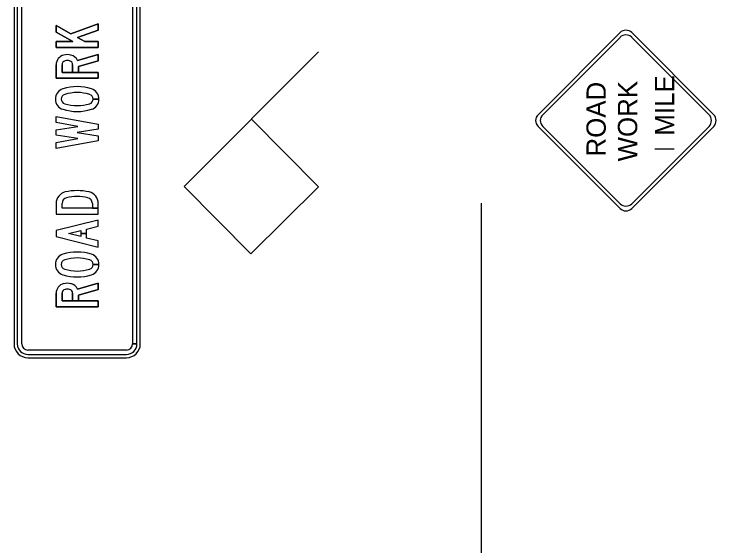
# Model space of a CAD drawing. Extents: x 2155255 to 2162649, y 140388 to 141878.
# Drawn here: x 2156921.6 to 2157021.8, y 141260.5 to 141336.3 of the extents above; entities that cross this region are included whole.
import ezdxf

# ---------------------------------------------------------------- set-up
doc = ezdxf.new("R2010")
doc.units = 0
for name, color, linetype in [('5', 7, 'Continuous'), ('Default', 7, 'Continuous'), ('GSBWFILL', 7, 'Continuous'), ('PR_Dimensions1', 7, 'Continuous'), ('PR_Traffic_Control_Devices_Temp', 7, 'Continuous')]:
    doc.layers.add(name, color=color, linetype=linetype)

# ---------------------------------------------------------------- blocks, each defined once
blk = doc.blocks.new('Cw20-1')
at = {"layer": '5'}
for p, q in [((0.318, 3.005), (2.651, 5.339)), ((5.338, 3.005), (3.005, 5.339)), ((2.651, 0.318), (0.318, 2.652)), ((3.005, 0.318), (5.338, 2.652))]:
    blk.add_line(p, q, dxfattribs=at)
for centre, start, end in [((2.828, 5.162), 45, 135), ((0.495, 2.828), 135, 225), ((5.162, 2.828), 315, 45), ((2.828, 0.495), 225, 315)]:
    blk.add_arc(centre, 0.25, start, end, dxfattribs=at)
at = {"layer": 'Default'}
for p, q in [((0.177, 3.005), (2.651, 5.48)), ((5.48, 3.005), (3.005, 5.48)), ((2.651, 0.177), (0.177, 2.652)), ((3.005, 0.177), (5.48, 2.652)), ((1.961, 1.37), (1.961, 1.953))]:
    blk.add_line(p, q, dxfattribs=at)
for centre, start, end in [((2.828, 5.303), 45, 135), ((0.353, 2.828), 135, 225), ((5.303, 2.828), 315, 45), ((2.828, 0.354), 225, 315)]:
    blk.add_arc(centre, 0.25, start, end, dxfattribs=at)
for s, p in [('ROAD', (1.743, 3.436)), ('WORK', (1.595, 2.487)), ('MILE', (2.372, 1.369))]:
    blk.add_text(s, height=0.5833, dxfattribs=at).set_placement(p)
blk = doc.blocks.new('FLSHFLAG')
at = {"layer": 'Default'}
for p, q in [((-1.202, 14.125), (0.838, 16.147)), ((0.838, 16.147), (4.9, 12.085)), ((0.819, 12.085), (-1.202, 14.125)), ((0.819, 12.085), (2.86, 14.106)), ((9.258, 14.004), (8.403, 13.149)), ((9.258, 14.004), (10.685, 12.576)), ((10.685, 12.576), (9.831, 11.722))]:
    blk.add_line(p, q, dxfattribs=at)
blk.add_circle((10.653, 13.836), 0.873, dxfattribs=at)

msp = doc.modelspace()

# ---------------------------------------------------------------- linework, layer by layer
at = {"layer": 'GSBWFILL'}
for p, q in [((2156932.82, 141324.18), (2156933.66, 141324.18)), ((2156933.66, 141324.18), (2156932.82, 141324.18)), ((2156927.56, 141320.83), (2156927.56, 141321.69)), ((2156927.56, 141321.69), (2156933.56, 141320.61)), ((2156930.66, 141320.28), (2156927.56, 141320.83)), ((2156927.56, 141319.78), (2156930.66, 141320.28)), ((2156933.56, 141320.61), (2156933.56, 141319.89)), ((2156927.56, 141319.04), (2156927.56, 141319.78)), ((2156933.56, 141319.89), (2156930.56, 141319.41)), ((2156930.56, 141319.41), (2156933.56, 141318.93)), ((2156930.66, 141318.54), (2156927.56, 141319.04)), ((2156927.56, 141317.98), (2156930.66, 141318.54)), ((2156933.56, 141318.93), (2156933.56, 141318.21)), ((2156933.56, 141318.21), (2156927.56, 141317.13)), ((2156927.56, 141317.13), (2156927.56, 141317.98)), ((2156932.72, 141309.3), (2156932.72, 141308.61)), ((2156932.82, 141300.6), (2156933.66, 141300.6)), ((2156933.66, 141300.6), (2156932.82, 141300.6))]:
    msp.add_line(p, q, dxfattribs=at)
for points in [[(2156921.56, 141399.34), (2156921.56, 141289.28)], [(2156922.02, 141399.34), (2156922.02, 141289.28)], [(2156922.02, 141399.34), (2156922.02, 141289.28)], [(2156922.65, 141289.28), (2156922.65, 141399.34)], [(2156922.65, 141289.28), (2156922.65, 141399.34)], [(2156938.46, 141399.34), (2156938.46, 141289.28), (2156939.09, 141289.28)], [(2156938.46, 141399.34), (2156938.46, 141289.28), (2156939.09, 141289.28)], [(2156939.09, 141289.28), (2156939.09, 141399.34)], [(2156939.09, 141289.28), (2156939.09, 141399.34)], [(2156939.56, 141289.28), (2156939.56, 141399.34)], [(2156927.56, 141332.37), (2156927.56, 141331.53), (2156933.56, 141331.53), (2156933.56, 141332.37), (2156931.64, 141332.37), (2156930.62, 141332.94), (2156933.56, 141334), (2156933.56, 141334.89), (2156929.66, 141333.49), (2156927.56, 141334.68), (2156927.56, 141333.71), (2156929.93, 141332.37), (2156927.56, 141332.37)], [(2156929.9, 141329.08), (2156929.9, 141327.99), (2156930.74, 141327.99), (2156930.74, 141328.83), (2156933.56, 141329.63), (2156933.56, 141330.51), (2156930.61, 141329.67)], [(2156930.61, 141329.67), (2156933.56, 141330.51), (2156933.56, 141329.63), (2156930.74, 141328.83), (2156930.74, 141327.99), (2156929.9, 141327.99), (2156929.9, 141329.08)], [(2156927.56, 141329.08), (2156927.56, 141327.15), (2156933.56, 141327.15), (2156933.56, 141327.99), (2156928.4, 141327.99), (2156928.4, 141329.08)], [(2156928.4, 141329.08), (2156928.4, 141327.99), (2156933.56, 141327.99), (2156933.56, 141327.15), (2156927.56, 141327.15), (2156927.56, 141329.08)], [(2156932.82, 141324.18), (2156933.66, 141324.18)], [(2156933.66, 141324.18), (2156932.82, 141324.18)], [(2156927.56, 141309.3), (2156927.56, 141307.77), (2156933.56, 141307.77), (2156933.56, 141308.61), (2156928.4, 141308.61), (2156928.4, 141309.3)], [(2156927.56, 141309.3), (2156927.56, 141307.77), (2156933.56, 141307.77), (2156933.56, 141308.61), (2156928.4, 141308.61), (2156928.4, 141309.3)], [(2156932.72, 141308.61), (2156933.56, 141308.61), (2156933.56, 141309.3)], [(2156932.72, 141308.61), (2156933.56, 141308.61), (2156933.56, 141309.3)], [(2156932.72, 141309.3), (2156932.72, 141308.61)], [(2156929.34, 141305.01), (2156931.07, 141305.44), (2156931.07, 141305.01), (2156931.91, 141305.01), (2156931.91, 141305.65), (2156933.56, 141306.06), (2156933.56, 141306.93), (2156927.56, 141305.43), (2156927.56, 141304.59), (2156933.56, 141303.09), (2156933.56, 141303.95), (2156931.91, 141304.37), (2156931.91, 141305.01), (2156931.07, 141305.01), (2156931.07, 141304.58), (2156929.34, 141305.01)], [(2156932.82, 141300.6), (2156933.66, 141300.6)], [(2156933.66, 141300.6), (2156932.82, 141300.6)], [(2156929.9, 141296.5), (2156929.9, 141295.41), (2156930.74, 141295.41), (2156930.74, 141296.25), (2156933.56, 141297.05), (2156933.56, 141297.93), (2156930.61, 141297.09)], [(2156930.61, 141297.09), (2156933.56, 141297.93), (2156933.56, 141297.05), (2156930.74, 141296.25), (2156930.74, 141295.41), (2156929.9, 141295.41), (2156929.9, 141296.5)], [(2156927.56, 141296.5), (2156927.56, 141294.57), (2156933.56, 141294.57), (2156933.56, 141295.41), (2156928.4, 141295.41), (2156928.4, 141296.5)], [(2156928.4, 141296.5), (2156928.4, 141295.41), (2156933.56, 141295.41), (2156933.56, 141294.57), (2156927.56, 141294.57), (2156927.56, 141296.5)], [(2156939.09, 141289.28), (2156938.46, 141289.28)], [(2156939.09, 141289.28), (2156938.46, 141289.28)], [(2156939.56, 141289.28), (2156939.56, 141289.28)], [(2156937.59, 141288.4), (2156923.52, 141288.4)], [(2156937.59, 141288.4), (2156923.52, 141288.4)], [(2156923.52, 141287.78), (2156937.59, 141287.78)], [(2156923.52, 141287.78), (2156937.59, 141287.78)], [(2156923.52, 141287.31), (2156937.59, 141287.31)]]:
    msp.add_lwpolyline(points, dxfattribs=at)
for points in [[(2156930.62, 141332.94), (2156931.64, 141332.37), (2156933.56, 141332.37), (2156933.56, 141331.53), (2156927.56, 141331.53), (2156927.56, 141332.37), (2156929.93, 141332.37), (2156927.56, 141333.71), (2156927.56, 141334.68), (2156929.66, 141333.49), (2156933.56, 141334.89), (2156933.56, 141334)], [(2156930.66, 141318.54), (2156927.56, 141319.04), (2156927.56, 141319.78), (2156930.66, 141320.28), (2156927.56, 141320.83), (2156927.56, 141321.69), (2156933.56, 141320.61), (2156933.56, 141319.89), (2156930.56, 141319.41), (2156933.56, 141318.93), (2156933.56, 141318.21), (2156927.56, 141317.13), (2156927.56, 141317.98)], [(2156931.07, 141305.01), (2156931.07, 141304.58), (2156929.34, 141305.01), (2156931.07, 141305.44), (2156931.07, 141305.01), (2156931.91, 141305.01), (2156931.91, 141305.65), (2156933.56, 141306.06), (2156933.56, 141306.93), (2156927.56, 141305.43), (2156927.56, 141304.59), (2156933.56, 141303.09), (2156933.56, 141303.95), (2156931.91, 141304.37), (2156931.91, 141305.01)]]:
    msp.add_lwpolyline(points, close=True, dxfattribs=at)
for centre, radius, start, end in [((2156928.97, 141329.08), 1.41, 103.8865, 180), ((2156928.97, 141329.08), 1.41, 103.8865, 180), ((2156929.15, 141328.35), 2.16, 76.1135, 103.8865), ((2156929.15, 141328.35), 2.16, 76.1135, 103.8865), ((2156929.33, 141329.08), 1.41, 24.8221, 76.1135), ((2156929.33, 141329.08), 1.41, 24.8221, 76.1135), ((2156928.97, 141329.08), 0.57, 103.8865, 180), ((2156928.97, 141329.08), 0.57, 103.8865, 180), ((2156929.15, 141328.35), 1.32, 76.1135, 103.8865), ((2156929.15, 141328.35), 1.32, 76.1135, 103.8865), ((2156929.33, 141329.08), 0.57, 360, 76.1135), ((2156929.33, 141329.08), 0.57, 360, 76.1135), ((2156928.98, 141324.18), 1.53, 107.3283, 252.6717), ((2156928.98, 141324.18), 1.53, 107.3283, 252.6717), ((2156930.56, 141319.13), 6.82, 72.6717, 107.3283), ((2156930.56, 141319.13), 6.82, 72.6717, 107.3283), ((2156932.13, 141324.18), 1.53, 0.0112, 72.6717), ((2156932.13, 141324.18), 1.53, 0.0112, 72.6717), ((2156928.98, 141324.18), 0.69, 107.3283, 252.6717), ((2156928.98, 141324.18), 0.69, 107.3283, 252.6717), ((2156930.56, 141319.13), 5.98, 72.6717, 107.3283), ((2156930.56, 141319.13), 5.98, 72.6717, 107.3283), ((2156932.13, 141324.18), 0.69, 0.0249, 72.6717), ((2156932.13, 141324.18), 0.69, 0.0249, 72.6717), ((2156930.56, 141329.23), 5.98, 252.6717, 287.3283), ((2156930.56, 141329.23), 5.98, 252.6717, 287.3283), ((2156932.13, 141324.18), 0.69, 287.3283, 0), ((2156932.13, 141324.18), 0.69, 287.3283, 0), ((2156932.13, 141324.18), 1.53, 287.3283, 360), ((2156932.13, 141324.18), 1.53, 287.3283, 360), ((2156930.56, 141329.23), 6.82, 252.6717, 287.3283), ((2156930.56, 141329.23), 6.82, 252.6717, 287.3283), ((2156929.24, 141309.3), 1.68, 103.109, 180), ((2156929.24, 141309.3), 1.68, 103.109, 180), ((2156930.56, 141303.63), 7.5, 76.891, 103.109), ((2156930.56, 141303.63), 7.5, 76.891, 103.109), ((2156930.56, 141303.63), 6.66, 76.891, 103.109), ((2156930.56, 141303.63), 6.66, 76.891, 103.109), ((2156931.88, 141309.3), 1.68, 360, 76.891), ((2156931.88, 141309.3), 1.68, 360, 76.891), ((2156929.24, 141309.3), 0.84, 103.109, 180), ((2156929.24, 141309.3), 0.84, 103.109, 180), ((2156931.88, 141309.3), 0.84, 360, 76.891), ((2156931.88, 141309.3), 0.84, 360, 76.891), ((2156930.56, 141295.55), 6.82, 72.6717, 107.3283), ((2156930.56, 141295.55), 6.82, 72.6717, 107.3283), ((2156928.98, 141300.6), 1.53, 107.3283, 252.6717), ((2156928.98, 141300.6), 1.53, 107.3283, 252.6717), ((2156928.98, 141300.6), 0.69, 107.3283, 252.6717), ((2156928.98, 141300.6), 0.69, 107.3283, 252.6717), ((2156930.56, 141295.55), 5.98, 72.6717, 107.3283), ((2156930.56, 141295.55), 5.98, 72.6717, 107.3283), ((2156932.13, 141300.6), 0.69, 0.0249, 72.6717), ((2156932.13, 141300.6), 0.69, 0.0249, 72.6717), ((2156932.13, 141300.6), 1.53, 0.0112, 72.6717), ((2156932.13, 141300.6), 1.53, 0.0112, 72.6717), ((2156932.13, 141300.6), 0.69, 287.3283, 0), ((2156932.13, 141300.6), 0.69, 287.3283, 0), ((2156932.13, 141300.6), 1.53, 287.3283, 360), ((2156932.13, 141300.6), 1.53, 287.3283, 360), ((2156930.56, 141305.65), 5.98, 252.6717, 287.3283), ((2156930.56, 141305.65), 5.98, 252.6717, 287.3283), ((2156930.56, 141305.65), 6.82, 252.6717, 287.3283), ((2156930.56, 141305.65), 6.82, 252.6717, 287.3283), ((2156928.97, 141296.5), 1.41, 103.8865, 180), ((2156928.97, 141296.5), 1.41, 103.8865, 180), ((2156929.15, 141295.77), 2.16, 76.1135, 103.8865), ((2156929.15, 141295.77), 2.16, 76.1135, 103.8865), ((2156929.33, 141296.5), 1.41, 24.8221, 76.1135), ((2156929.33, 141296.5), 1.41, 24.8221, 76.1135), ((2156928.97, 141296.5), 0.57, 103.8865, 180), ((2156928.97, 141296.5), 0.57, 103.8865, 180), ((2156929.15, 141295.77), 1.32, 76.1135, 103.8865), ((2156929.15, 141295.77), 1.32, 76.1135, 103.8865), ((2156929.33, 141296.5), 0.57, 360, 76.1135), ((2156929.33, 141296.5), 0.57, 360, 76.1135), ((2156923.52, 141289.28), 1.97, 180, 270), ((2156923.52, 141289.28), 1.5, 180, 270), ((2156923.52, 141289.28), 1.5, 180, 270), ((2156923.52, 141289.28), 0.875, 180, 270), ((2156923.52, 141289.28), 0.875, 180, 270), ((2156937.59, 141289.28), 1.5, 270, 0), ((2156937.59, 141289.28), 0.875, 270, 360), ((2156937.59, 141289.28), 1.5, 270, 0), ((2156937.59, 141289.28), 0.875, 270, 360), ((2156937.59, 141289.28), 1.97, 270, 0)]:
    msp.add_arc(centre, radius, start, end, dxfattribs=at)
at = {"layer": 'PR_Dimensions1'}
msp.add_line((2156988.21, 141198.84), (2156988.21, 141309.35), dxfattribs=at)

# ---------------------------------------------------------------- block references
at = {"layer": 'PR_Traffic_Control_Devices_Temp', "xscale": 4.7244, "yscale": 4.7244, "rotation": 90}
for name, p in [('FLSHFLAG', (2157022.08, 141307.78)), ('Cw20-1', (2157022.18, 141307.76))]:
    msp.add_blockref(name, p, dxfattribs=at)

doc.saveas('drawing.dxf')
